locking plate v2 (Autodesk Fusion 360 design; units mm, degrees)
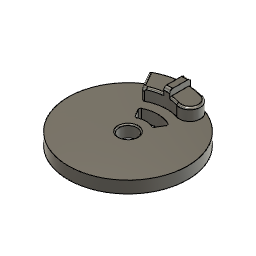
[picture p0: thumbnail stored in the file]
sketch "Sketch1" plane through (0, 0, 0) normal (0, 1, 0) x axis (1, 0, 0)
  circle C1 centre (0, 0) radius 50
  point P1 (0, 0)
  point P2 (0, 0)
  coincident P1 P2
  dimension "d1" diameter C1 = 100
extrude "Extrude1" new body sketch "Sketch1" along normal blind 10
sketch "Sketch2" plane through (0, 10, 0) normal (0, 1, 0) x axis (-1, 0, 0)
  line L1 (-16.25, -28.1458) -> (-25, -43.3013)
  line L2 (25, -43.3013) -> (16.25, -28.1458)
  line L3 (0, -32.5) -> (0, 0)
  circle C1 centre (0, 0) radius 50
  circle C2 centre (0, 0) radius 32.5
  point P4 (-25, -43.3013)
  point P5 (-16.25, -28.1458)
  point P6 (16.25, -28.1458)
  point P7 (25, -43.3013)
  point P3 (0, 0)
  point P8 (0, 0)
  point P9 (0, -32.5)
  point P1 (0, 0)
  concentric C1 C2
  coincident C1 P4
  coincident C2 P5
  coincident C2 P6
  coincident C1 P7
  coincident P3 P8
  coincident C2 P9
  vertical L3
  coincident P1 L1
  coincident P3 L2
  dimension "d4" diameter C2 = 65
  dimension "d5" angle L1 L3 = 30
  dimension "d6" angle L2 L3 = 30 (= "d5")
extrude "Extrude2" add sketch "Sketch2" profile of C1 C2 L1 L2 along normal blind 10
sketch "Sketch3" plane through (0, 10, 0) normal (0, 1, 0) x axis (-1, 0, 0)
  line L1 (25, -43.3013) -> (16.25, -28.1458)
  line L2 (-16.25, -28.1458) -> (-25, -43.3013)
  line L3 (-25, -43.3013) -> (-16.25, -28.1458)
  line L4 (16.25, -28.1458) -> (25, -43.3013)
  line L5 (-12.5, -21.6506) -> (-7.5, -12.9904)
  line L6 (12.5, -21.6506) -> (7.5, -12.9904)
  arc A1 centre (0, 0) radius 50 clockwise from (-25, -43.3013) to (25, -43.3013)
  arc A2 centre (0, 0) radius 32.5 clockwise from (16.25, -28.1458) to (-16.25, -28.1458)
  circle C1 centre (0, 0) radius 25
  circle C2 centre (0, 0) radius 15
  point P13 (-7.5, -12.9904)
  point P14 (-12.5, -21.6506)
  point P16 (12.5, -21.6506)
  point P15 (7.5, -12.9904)
  concentric A1 C1
  concentric C1 C2
  coincident C2 P13
  coincident C1 P14
  coincident C1 P16
  coincident C2 P15
  collinear L1 L6
  collinear L3 L5
  dimension "d9" diameter C2 = 30
  dimension "d10" diameter C1 = 50
extrude "Extrude3" cut sketch "Sketch3" profile of C1 C2 L5 L6 no distance stored
sketch "Sketch4" plane through (0, 10, 0) normal (0, 1, 0) x axis (-1, 0, 0)
  line L1 (12.5, -21.6506) -> (7.5, -12.9904)
  line L2
  line L3 (25, -43.3013) -> (16.25, -28.1458)
  line L4 (-16.25, -28.1458) -> (-25, -43.3013)
  arc A1 centre (0, 0) radius 15 clockwise from (7.5, -12.9904) to (-7.5, -12.9904)
  arc A2 centre (0, 0) radius 25 clockwise from (12.5, -21.6506) to (-12.5, -21.6506)
  arc A3 centre (0, 0) radius 50 clockwise from (-25, -43.3013) to (25, -43.3013)
  arc A4 centre (0, 0) radius 32.5 clockwise from (16.25, -28.1458) to (-16.25, -28.1458)
  circle C1 centre (0, 0) radius 7.5
  concentric A1 C1
  dimension "d12" diameter C1 = 15
extrude "Extrude4" cut sketch "Sketch4" profile of C1 no distance stored
sketch "Sketch5" plane through (0, 20, 0) normal (0, 1, 0) x axis (-1, 0, 0)
  line L1 (16.25, -28.1458) -> (25, -43.3013)
  line L2 (-25, -43.3013) -> (-16.25, -28.1458)
  line L3 (-2.5, -55) -> (2.5, -55)
  line L4 (-2.5, -30) -> (-2.5, -55)
  line L5 (2.5, -30) -> (-2.5, -30)
  line L6 (2.5, -55) -> (2.5, -30)
  line L7 (-2.5, -30) -> (2.5, -55)
  line L8 (2.5, -30) -> (-2.5, -55)
  arc A1 centre (0, 0) radius 50 clockwise from (25, -43.3013) to (-25, -43.3013)
  arc A2 centre (0, 0) radius 32.5 clockwise from (16.25, -28.1458) to (-16.25, -28.1458)
  point P11 (0, -42.5)
  point P1 (0, 0)
  point P7 (2.5, -55)
  point P8 (-2.5, -55)
  point P9 (-2.5, -30)
  perpendicular L3 L4
  parallel L3 L5
  parallel L4 L6
  horizontal L3
  coincident L7 P11
  coincident L8 P11
  vertical P1 P11
  dimension "d14" distance P7 P8 = 5
  dimension "d15" distance P8 P9 = 25
  dimension "d16" distance P1 P9 = 30
extrude "Extrude5" add sketch "Sketch5" profile of A1 A2 L4 L6 along normal blind 5
fillet "Fillet1" radius 1.5
fillet "Fillet2"
fillet "Fillet3" radius 1.5
fillet "Fillet4" radius 1.5
fillet "Fillet5" radius 1.5
fillet "Fillet6" radius 2.5 1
